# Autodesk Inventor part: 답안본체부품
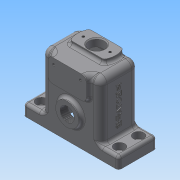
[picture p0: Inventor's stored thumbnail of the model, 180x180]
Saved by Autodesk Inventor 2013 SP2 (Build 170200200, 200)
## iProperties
Created: 2023-12
Part Number: 답안본체부품
Material: Generic
Document SubType Name: Modeling
Designer: i
Density: 1 g/cm^3
Author: i
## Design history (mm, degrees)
sketch "스케치1"
  geometry: L1 (-50, 20)-(50, 20); L2 (50, 20)-(50, -20); L3 (50, -20)-(-50, -20); L4 (-50, -20)-(-50, 20); L5 (-50, 20)-(50, -20); L6 (50, 20)-(-50, -20); 1 further point
  constraints: 12 end point, 2 midpoint, 2 parallel, 1 horizontal, 1 perpendicular
  dimensions: "d0" = 100 distance of L2.end L3.end; "d1" = 40 distance of L1.end L2.end
extrude "돌출1" new body sketch "스케치1" distance "d2" = 12; taper "d3" = 0 deg
sketch "스케치2"
  geometry: L1 (50, 12)-(50, 0) reference; L2 (50, 0)-(-50, 0) reference; L3 (-50, 0)-(-50, 12) reference; L4 (-50, 12)-(50, 12) reference; L5 (50, 12)-(-50, 12) reference; L6 (-31, 12)-(31, 12); L7 (31, 12)-(31, 72); L8 (31, 72)-(-31, 72); L9 (-31, 72)-(-31, 12); 3 further points
  constraints: 8 end point, 2 midpoint, 2 parallel, 1 horizontal, 1 perpendicular, 1 point on line, 1 vertical alignment
  dimensions: "d4" = 62 distance of L7.end L8.end; "d6" = 72 distance between parallel lines of L8 L2
extrude "돌출2" join sketch "스케치2" stored distance "d7" = 40; taper "d9" = 0 deg; dims "d8" = 20, "d10" = 0
sketch "스케치3"
  geometry: L1 (-31, -72)-(31, -72) reference; L2 (20, -72)-(-20, -72); L3 (-20, -72)-(-20, -48); L4 (-20, -48)-(20, -48); L5 (20, -48)-(20, -72); 3 further points
  constraints: 8 end point, 2 midpoint, 2 parallel, 1 horizontal, 1 perpendicular, 1 point on line, 1 vertical alignment
  dimensions: "d11" = 40 distance of L3.end L4.end; "d13" = 24 distance of L2.end L3.end
extrude "돌출3" join sketch "스케치3" distance "d14" = 4; taper "d15" = 0 deg
sketch "스케치4"
  geometry: L1 (0, 0)-(100, 0) reference; L2 (0, -12)-(0, 0) reference; L3 (0, 0)-(100, 0) reference; L4 (100, 0)-(100, -12) reference; L5 (100, -12)-(81, -12) reference; L6 (81, -12)-(81, -72) reference; L7 (81, -72)-(70, -72) reference; L8 (70, -72)-(30, -72) reference; L9 (30, -72)-(19, -72) reference; L10 (19, -72)-(19, -12) reference; L11 (19, -12)-(0, -12) reference; L12 (70, -48)-(70, -72) reference; L13 (30, -48)-(70, -48) reference; L14 (30, -72)-(30, -48) reference; C1 r 12 at (50, -28); 1 further point
  constraints: 1 centre point
  dimensions: "d16" = 28 distance from line of L1 C1.centre; "d17" = 24 diameter of C1
extrude "돌출4" join sketch "스케치4" distance "d18" = 4; taper "d19" = 0 deg
sketch "스케치5"
  geometry: L1 (11, 44)-(51, 44) reference; L2 (55, 3)-(48.321, 3); L3 (7, 3)-(7, 23); L4 (7, 23)-(13.679, 23); L5 (55, 23)-(55, 3); L6 (55, 3)-(7, 23); L7 (7, 3)-(55, 23); L8 (48.321, 3)-(13.679, 3); L9 (48.321, 23)-(55, 23); L10 (13.679, 23)-(48.321, 23); L11 (13.679, 3)-(7, 3); A1 r 20 centre (31, 13) between (48.321, 3) and (48.321, 23); A2 r 20 centre (31, 13) between (13.679, 23) and (13.679, 3); 1 further point
  constraints: 20 end point, 10 parallel, 4 point on circle, 3 horizontal, 3 perpendicular, 2 centre point, 2 midpoint, 1 point on line, 1 vertical alignment
  dimensions: "d22" = 20 distance of L3.start L3.end; "d23" = 31 distance from line of L1 A1.centre; "d24" = 48 distance of L2.start L3.start; "d25" = 20 radius of A2; "d26" = 20 radius of A1
extrude "돌출5" join sketch "스케치5" distance "d27" = 4; taper "d28" = 0 deg
sketch "스케치6"
  geometry: L1 (50, 20)-(50, -20) reference; L2 (50, -20)-(31, -20) reference; L3 (31, 20)-(31, -20) reference; L4 (-31, 20)-(31, 20) reference; L5 (-31, -20)-(-31, 20) reference; L6 (-31, -20)-(-50, -20) reference; L7 (-50, -20)-(-50, 20) reference; L8 (-50, 20)-(-31, 20) reference; L9 (31, 20)-(50, 20) reference; L10 (31, -20)-(-31, -20) reference; L11 (0, 20)-(0, -20); 5 further points
  constraints: 2 end point, 2 midpoint, 2 symmetric about line
  dimensions: "d29" = 20 distance of point (-41, -10) point (-41, 10); "d31" = 10 distance from line of L6 point (-41, -10); "d32" = 82 distance of point (41, 10) point (-41, 10); "d33" = 82 distance of point (41, -10) point (-41, -10)
hole "구멍1" sketch "스케치6" at (-41, 10), (-41, -10), (41, 10), (41, -10) diameter "d34" = 6.6; stored, may be unused: countersink angle "d38" = 90 deg, drill point angle "d40" = 118 deg; dims "d35" = 6.6, "d36" = 11, "d37" = 6.6, "d39" = 8
sketch "스케치7"
  geometry: L1 (100, 0)-(0, 0) reference; C1 r 20 at (50, 28); 2 further points
  constraints: 1 centre point, 1 midpoint, 1 vertical alignment
  dimensions: "d41" = 40 diameter of C1; "d42" = 28 distance from line of C1.centre L1
extrude "돌출6" join sketch "스케치7" distance "d43" = 4; taper "d44" = 0 deg
sketch "스케치8"
  geometry: L1 (-27, 16)-(27, 16); L2 (27, 16)-(27, -16); L3 (27, -16)-(-27, -16); L4 (-27, -16)-(-27, 16); L5 (-27, 16)-(27, -16); L6 (27, 16)-(-27, -16); 1 further point
  constraints: 12 end point, 2 midpoint, 2 parallel, 1 horizontal, 1 perpendicular
  dimensions: "d45" = 32 distance of L1.end L2.end; "d47" = 54 distance of L2.end L3.end
extrude "돌출7" cut sketch "스케치8" distance "d48" = 68; taper "d49" = 0 deg
sketch "스케치9"
  geometry: C1 r 8 at (31, 13); A1 r 20 centre (31, 13) between (13.679, 23) and (13.679, 3) reference; 1 further point
  constraints: 1 centre point, 1 coincident
  dimensions: "d50" = 16 diameter of C1
extrude "돌출8" cut sketch "스케치9" stored distance "d51" = 68; taper "d52" = 0 deg
sketch "스케치10"
  geometry: C1 r 20 at (0, 0) reference; C2 r 9 at (0, 0); 1 further point
  constraints: 1 centre point, 1 coincident
  dimensions: "d53" = 18 diameter of C2
extrude "돌출9" cut sketch "스케치10" stored distance "d54" = 68; taper "d55" = 0 deg
sketch "스케치11" dims "d56" = 30
  geometry: L1 (0, 0)-(0, 15); L2 (0, 0)-(-15, 0); L3 (0, 0)-(0, -15); L4 (0, 0)-(15, 0); C1 r 9 at (0, 0) reference; C2 r 20 at (0, 0) reference; 5 further points
  constraints: 8 end point, 5 coincident, 2 horizontal alignment, 2 vertical alignment, 1 vertical, 29 other
  dimensions: "d59" = 360 deg dimension on C1.centre L1.end (derived)
hole "구멍2" sketch "스케치11" at (0, 15), (-15, 0), (0, -15), (15, 0) diameter "d61" = 2.459; stored, may be unused: countersink angle "d65" = 90 deg, drill point angle "d67" = 118 deg; dims "d62" = 6.6, "d63" = 11, "d64" = 6.6, "d66" = 8
sketch "스케치12"
  geometry: L1 (20, -72)-(31, -72) reference; L2 (-31, -72)-(-20, -72) reference; 3 further points
  dimensions: "d68" = 28 distance of point (-14, -66) point (14, -66); "d70" = 6 distance from line of point (14, -66) L1; "d71" = 6 distance from line of L2 point (-14, -66); "d72" = 14 horizontal distance of point (0, 0) point (14, -66)
hole "구멍3" sketch "스케치12" at (14, -66), (-14, -66) diameter "d73" = 2.459; stored, may be unused: countersink angle "d77" = 90 deg, drill point angle "d79" = 118 deg; dims "d74" = 6.6, "d75" = 11, "d76" = 6.6, "d78" = 8
sketch "스케치13"
  geometry: C1 r 8 at (31, 13) reference; 3 further points
  constraints: 2 horizontal alignment
  dimensions: "d80" = 28 distance of point (17, 13) point (45, 13); "d82" = 14 distance of point (45, 13) C1.centre
hole "구멍4" sketch "스케치13" at (45, 13), (17, 13) diameter "d83" = 2.459; stored, may be unused: countersink angle "d87" = 90 deg, drill point angle "d89" = 118 deg; dims "d84" = 6.6, "d85" = 11, "d86" = 6.6, "d88" = 8
hole "구멍5" diameter "d92" = 14.917; stored, may be unused: countersink angle "d96" = 90 deg, drill point angle "d98" = 118 deg; dims "d93" = 6.6, "d94" = 11, "d95" = 6.6, "d97" = 8, "d99" = 10, "d100" = 10
fillet "모깎기5" dims "d105" = 3
fillet "모깎기7" dims "d107" = 3
fillet "모깎기8" dims "d108" = 3
fillet "모깎기10" dims "d110" = 7
fillet "모깎기11" dims "d111" = 7
fillet "모깎기12" dims "d112" = 3
fillet "모깎기13" dims "d113" = 7
fillet "모깎기14" dims "d114" = 3
fillet "모깎기15" dims "d115" = 5
fillet "모깎기16" dims "d116" = 3
chamfer "모따기1" distance "d118" = 1; stored, may be unused: second distance "d119" = 2, angle "d120" = 45 deg
sketch "스케치14"
  geometry: L1 (-39.238, 17.002)-(-10.762, 17.002); L2 (-10.762, 17.002)-(-10.762, 10.998); L3 (-10.762, 10.998)-(-39.238, 10.998); L4 (-39.238, 10.998)-(-39.238, 17.002); L5 (-39.238, 14)-(-10.762, 14); L6 (-25, 17.002)-(-25, 10.998); L7 (-65, -7)-(-65, 33) reference; L8 (-25, 37)-(-49, 37) reference; 3 further points
  constraints: 4 end point, 4 midpoint, 2 other
  dimensions: "d121" = 40 distance between parallel lines of L7 L6; "d122" = 23 distance between parallel lines of L8 L5
feature "엠보싱1" sketch "스케치14" dims "d0" = 100, "d1" = 40, "d123" = 0.5, "d124" = 0
fillet "모깎기18" dims "d125" = 3
fillet "모깎기19" dims "d126" = 3
fillet "모깎기20" dims "d127" = 3
node "솔리드1"
node "절단 모서리 투영1"
node "절단 모서리 투영2"
node "절단 모서리 투영3"
